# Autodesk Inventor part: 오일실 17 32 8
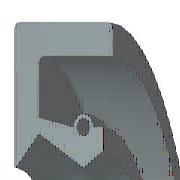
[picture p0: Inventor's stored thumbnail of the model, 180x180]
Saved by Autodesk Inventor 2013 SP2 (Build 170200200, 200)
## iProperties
IsCustomPart: 1
Created: 2012-02
Part Number: 오일실 17 32 8
Material: 고무
Description: 오일-실
Document SubType Name: Modeling
Standard: KS B 2804
Designer: mduedu
Standards Organization: KS
Language: ko-KR
Size Designation: D - 17 32 8
Categories: <MemberInstance><Categories><Category DisplayName="샤프트 부품" InternalName="7f7aeb1f-a693-4053-b835-cee3144e0d98" Mnemonic="SHFT"><Category DisplayName="실링" Intern
Density: 0.93 g/cm^3
Author: mduedu
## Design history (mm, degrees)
revolve "본체" stored, may be unused: angle "d17" = 90 deg
revolve "스프링1" stored, may be unused: angle "d18" = 90 deg
body "Solid1"
sketch "스케치1"
  geometry: L1 (0, 16)-(8, 16); L2 (8, 14.25)-(1.75, 14.25); L3 (1.75, 10.25)-(4.9, 8.5); L4 (4.9, 8.5)-(0, 8.5); L5 (0, 0)-(9.586, 0) reference; L6 (4.9, 8.5)-(6.3, 9.375); L7 (0, 18)-(0, -3) reference; L8 (-1.941, 0)-(11.507, 0) reference; L9 (4.2, 10.6)-(1.75, 11.21); L10 (1.75, 11.21)-(1.75, 14.25); L11 (0, 16)-(0, 8.588); L12 (4.9, 8.5)-(0, 8.5); L13 (1.75, 10.25)-(0.152, 8.528); L14 (8, 16)-(8, 14.25); L15 (5.6, 10.6)-(6.3, 10.6); L16 (6.3, 10.6)-(6.3, 9.375); C1 r 0.455 at (4.9, 10.6); A1 r 0.7 centre (4.9, 10.6) between (5.6, 10.6) and (4.2, 10.6); A2 r 0.088 centre (0.088, 8.588) between (0, 8.588) and (0.152, 8.528); 1 further point
  constraints: 28 end point, 5 horizontal alignment, 5 point on line, 4 point on circle, 4 vertical alignment, 3 centre point, 3 tangent, 2 collinear, 2 horizontal, 2 perpendicular, 1 coincident, 1 parallel
  dimensions: "d0" = 32 diameter of L1 L5 (= SD2); "d1" = 1.75 distance of L1.end L2.start (= SD); "d2" = 0.91 diameter of C1 (= SPDI); "d3" = 1.4 diameter of A1 (= SPDA); "d4" = 17 diameter of L3.end L5 (= NND); "d5" = 20.5 diameter of L3.start L5 (= TKDM); "d7" = 22.42 diameter of L9.end L5 (= TKDM + 0.24 x SWDT); "d8" = 1.75 distance between parallel lines of L11 L10 (= SD); "d9" = 4.9 distance from line of L11 C1.centre (= SPDST); "d10" = 21.2 diameter of C1.centre L5 (= HLDM); "d11" = 0.0875 radius of A2 (= 0.25 x LAB); "d12" = 6.3 distance between parallel lines of L11 L16 (= SDI); "d13" = 18.75 diameter of L6.end L5 (= ABDM); "d14" = 8 distance from line of L11 L1.end (= SWDT)
fillet "모깎기1" dims "d6" = 0.3 (= RR)
other parameters: "SD2" = 32 [user parameter; used in 1 equation term], "SWDT" = 8 [user parameter; used in 2 equation terms], "RR" = 0.3 [user parameter; used in 1 equation term], "SD" = 1.75 [user parameter; used in 2 equation terms], "NND" = 17 [user parameter; used in 1 equation term], "SPDA" = 1.4 [user parameter; used in 1 equation term], "SPDI" = 0.91 [user parameter; used in 1 equation term], "TKDM" = 20.5 [user parameter; used in 2 equation terms], "HLDM" = 21.2 [user parameter; used in 1 equation term], "ABDM" = 18.75 [user parameter; used in 1 equation term], "SDI" = 6.3 [user parameter; used in 1 equation term], "SPDST" = 4.9 [user parameter; used in 1 equation term], "LAB" = 0.35 [user parameter; used in 1 equation term], "d15" = 0, "d16" = 0, "d19" = 0
